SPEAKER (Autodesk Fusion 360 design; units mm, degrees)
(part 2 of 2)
sketch "Sketch18" plane through (0, 0, 0) normal (0, 0, 1) x axis (1, 0, 0)
  line L1 (225, 0) -> (25, 0)
  line L2 (225, 24.87) -> (225, 0)
  line L3 (230.33, 24.87) -> (225, 24.87)
  line L4 (230.33, 35.13) -> (230.33, 24.87)
  line L5 (225, 35.13) -> (230.33, 35.13)
  line L6 (225, 60) -> (225, 35.13)
  line L7 (25, 60) -> (225, 60)
  line L8 (25, 35.3045) -> (25, 60)
  line L9 (19.67, 35.3045) -> (25, 35.3045)
  line L10 (19.67, 24.695) -> (19.67, 35.3045)
  line L11 (25, 24.695) -> (19.67, 24.695)
  line L12 (25, 0) -> (25, 24.695)
copy_paste_bodies "CopyPasteBodies1"
move "Move2"
copy_paste_bodies "CopyPasteBodies2"
move "Move3"
align "Align1"
align "Align2"
align "Align3"
component_from_bodies "Body->Comp1"
component_from_bodies "Body->Comp2"
component_from_bodies "Body->Comp3"
component_from_bodies "Body->Comp4"
align "Align1"
align "Align1"
align "Align1"
align "Align1"
move "Move1"
sketch "Sketch38" plane through (0, 0, 64) normal (0, 0, 1) x axis (-1, 0, 0)
  line L1 (35.33, -39.6999) -> (35.33, 80.3001)
  line L2 (40.33, -39.6999) -> (35.33, -39.6999)
  line L3 (40.33, 80.3001) -> (40.33, -39.6999)
  line L4 (35.33, 80.3001) -> (40.33, 80.3001)
  line L5 (-170, -39.6999) -> (40.33, -39.6999)
  line L6 (-170, 80) -> (-170, -39.6999)
  line L7 (40.33, 80) -> (-170, 80)
  line L8 (40.33, -39.6999) -> (40.33, 80)
  point P4 (40.33, -39.6999)
  point P6 (40.33, -39.6999)
  horizontal L5
  vertical L6
  horizontal L7
  vertical L8
  coincident P4 P6
extrude "Extrude1" add sketch "Sketch38" profile of L1 L5 L6 L7 along normal blind 5
extrude "Extrude2" add of existing geometry blind 5
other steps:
base_feature "Base Feature1"
base_feature "Base Feature1"
base_feature "Base Feature1"
base_feature "Base Feature1"
move "Move1"
move "Move1"
move "Move1"
base_feature "Base Feature1"
base_feature "Base Feature2"
base_feature "Base Feature1"
base_feature "Base Feature2"
base_feature "Base Feature3"
base_feature "Base Feature4"
base_feature "Base Feature5"
create_component "CreateComponent1"
create_component "CreateComponent1"
remove_body "RemoveBody1"
create_component "CreateComponent2"
remove_body "RemoveBody2"
create_component "CreateComponent3"
remove_body "RemoveBody3"
create_component "CreateComponent4"
remove_body "RemoveBody4"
